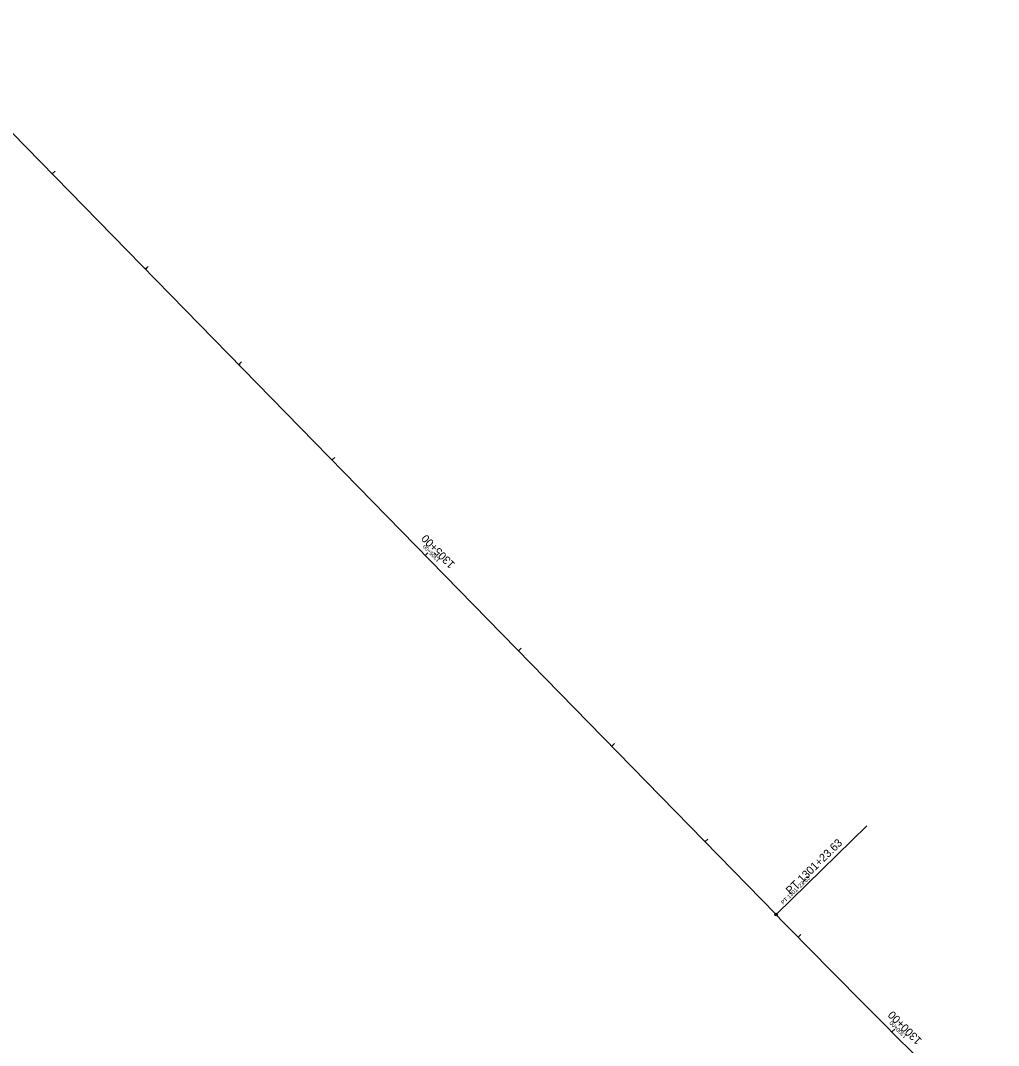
# Model space of a CAD drawing. Extents: x 2252205 to 2259955, y 13788514 to 13798103.
# Drawn here: x 2258518 to 2259251, y 13789350 to 13790118 of the extents above; entities that cross this region are included whole.
import ezdxf

# ---------------------------------------------------------------- set-up
doc = ezdxf.new("R2010")
doc.units = 0
for name, color, linetype in [('GEOM_CENTERLINE_ALIGN', 7, 'Continuous'), ('GEOM_CENTERLINE_PCPT_100', 7, 'Continuous'), ('GEOM_CENTERLINE_PCPT_50', 7, 'Continuous'), ('GEOM_CENTERLINE_STA_100', 7, 'Continuous'), ('GEOM_CENTERLINE_STA_50', 7, 'Continuous')]:
    doc.layers.add(name, color=color, linetype=linetype)

msp = doc.modelspace()

# ---------------------------------------------------------------- linework, layer by layer
at = {"layer": 'GEOM_CENTERLINE_ALIGN'}
msp.add_line((2259084.43, 13789447.87), (2256921.59, 13791662.1), dxfattribs=at)
msp.add_arc((2267281.84, 13797455.04), 11459.16, 224.327385, 225.508134, dxfattribs=at)
at = {"layer": 'GEOM_CENTERLINE_PCPT_100'}
msp.add_line((2259085.14, 13789448.57), (2259152.54, 13789514.4), dxfattribs=at)
at = {"layer": 'GEOM_CENTERLINE_PCPT_50'}
msp.add_line((2259084.78, 13789448.22), (2259118.48, 13789481.14), dxfattribs=at)
at = {"layer": 'GEOM_CENTERLINE_STA_100'}
for p, q in [((2258541.93, 13790003.26), (2258544.08, 13790005.35)), ((2258611.81, 13789931.72), (2258613.95, 13789933.82)), ((2258681.68, 13789860.18), (2258683.83, 13789862.28)), ((2258751.56, 13789788.65), (2258753.71, 13789790.74)), ((2258821.44, 13789717.11), (2258823.58, 13789719.21)), ((2258891.31, 13789645.58), (2258893.46, 13789647.67)), ((2258961.19, 13789574.04), (2258963.33, 13789576.14)), ((2259031.06, 13789502.5), (2259033.21, 13789504.6)), ((2259100.96, 13789430.99), (2259103.1, 13789433.09)), ((2259171.29, 13789359.9), (2259173.41, 13789362.02))]:
    msp.add_line(p, q, dxfattribs=at)
msp.add_circle((2259084.43, 13789447.87), 1, dxfattribs=at)
at = {"layer": 'GEOM_CENTERLINE_STA_50'}
for p, q in [((2258541.93, 13790003.26), (2258543.01, 13790004.3)), ((2258611.81, 13789931.72), (2258612.88, 13789932.77)), ((2258681.68, 13789860.18), (2258682.76, 13789861.23)), ((2258751.56, 13789788.65), (2258752.63, 13789789.7)), ((2258821.44, 13789717.11), (2258822.51, 13789718.16)), ((2258891.31, 13789645.58), (2258892.38, 13789646.62)), ((2258961.19, 13789574.04), (2258962.26, 13789575.09)), ((2259031.06, 13789502.5), (2259032.14, 13789503.55)), ((2259100.96, 13789430.99), (2259102.03, 13789432.04)), ((2259171.29, 13789359.9), (2259172.35, 13789360.96))]:
    msp.add_line(p, q, dxfattribs=at)
msp.add_circle((2259084.43, 13789447.87), 0.5, dxfattribs=at)

# ---------------------------------------------------------------- texts
at = {"layer": 'GEOM_CENTERLINE_PCPT_100'}
msp.add_text('PT 1301+23.63', height=6, rotation=44.32739, dxfattribs=at).set_placement((2259095.21, 13789462.6))
at = {"layer": 'GEOM_CENTERLINE_PCPT_50'}
msp.add_text('PT 1301+23.63', height=3, rotation=44.32739, dxfattribs=at).set_placement((2259089.82, 13789455.23))
at = {"layer": 'GEOM_CENTERLINE_STA_100'}
for s, rotation, p in [('1305+00', 134.32739, (2258844.24, 13789710.94)), ('1300+00', 134.94554, (2259194.15, 13789353.98))]:
    msp.add_text(s, height=6, rotation=rotation, dxfattribs=at).set_placement(p)
at = {"layer": 'GEOM_CENTERLINE_STA_50'}
for s, rotation, p in [('1305+00', 134.32739, (2258832.84, 13789714.03)), ('1300+00', 134.94554, (2259182.72, 13789356.94))]:
    msp.add_text(s, height=3, rotation=rotation, dxfattribs=at).set_placement(p)

doc.saveas('drawing.dxf')
